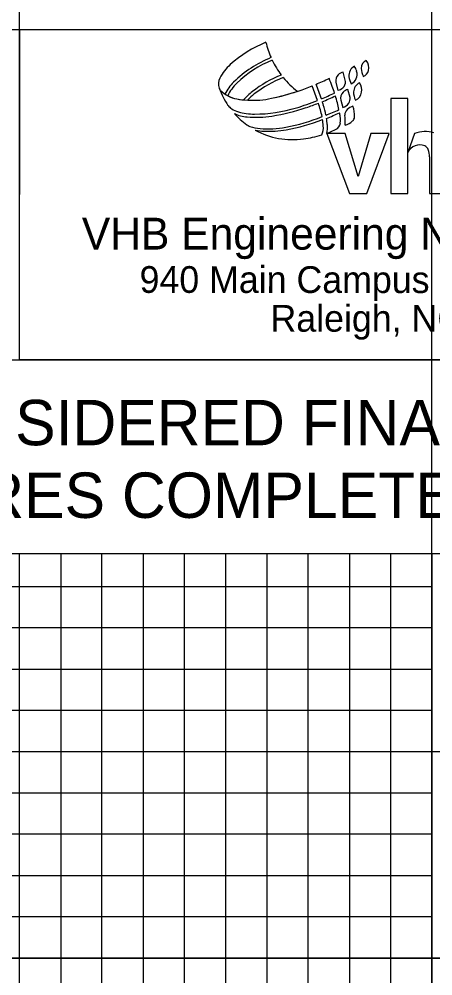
# Model space of a CAD drawing. Extents: x 1637092 to 1638792, y 884647 to 885778.
# Drawn here: x 1638666.6 to 1638716.8, y 885470 to 885585.9 of the extents above; entities that cross this region are included whole.
import ezdxf

# ---------------------------------------------------------------- set-up
doc = ezdxf.new("R2010")
doc.units = 0
for name, color, linetype in [('Default', 7, 'Continuous'), ('Scratch_Level_3', 7, 'Continuous'), ('Sheet DOT Grid CELL', 7, 'Continuous'), ('Sheet Layout Profile Border Port 1', 7, 'Continuous'), ('Sheet Plan And Profile CELL', 7, 'Continuous'), ('Sheet Profile CELL', 7, 'Continuous'), ('Sheet Profile Grid Major CELL', 7, 'Continuous'), ('Sheet Profile Grid Middle CELL', 7, 'Continuous'), ('Sheet Profile Grid Minor CELL', 7, 'Continuous')]:
    doc.layers.add(name, color=color, linetype=linetype)

msp = doc.modelspace()

# ---------------------------------------------------------------- linework, layer by layer
at = {"layer": 'Default'}
for p, q in [((1638706.2, 885578.33), (1638705.89, 885579.44)), ((1638705, 885578.23), (1638705.27, 885577.24)), ((1638702.77, 885576.02), (1638702.14, 885577.78)), ((1638706.75, 885576.37), (1638706.47, 885577.34)), ((1638705.6, 885576.04), (1638705.86, 885575.15)), ((1638713.75, 885576.25), (1638711.68, 885576.25)), ((1638711.68, 885576.25), (1638711.68, 885564.73)), ((1638703.92, 885572.02), (1638704.98, 885572.49)), ((1638706.14, 885572.02), (1638703.92, 885572.02)), ((1638703.92, 885572.02), (1638706.66, 885564.73)), ((1638707.71, 885566.81), (1638706.14, 885572.02)), ((1638709.27, 885572.02), (1638707.71, 885566.81)), ((1638708.75, 885564.73), (1638711.49, 885572.02)), ((1638711.49, 885572.02), (1638709.27, 885572.02)), ((1638714.56, 885572.02), (1638713.75, 885569.71)), ((1638716.36, 885569.18), (1638716.36, 885564.73)), ((1638706.66, 885564.73), (1638708.75, 885564.73)), ((1638711.68, 885564.73), (1638713.75, 885564.73)), ((1638716.36, 885564.73), (1638718.44, 885564.73)), ((1638566.62, 885544.59), (1638766.66, 885544.59)), ((1638566.62, 885544.59), (1638766.66, 885544.59)), ((1638766.66, 885521.09), (1638566.62, 885521.09)), ((1638766.66, 885521.09), (1638566.62, 885521.09))]:
    msp.add_line(p, q, dxfattribs=at)
msp.add_lwpolyline([(1638666.66, 885584.59), (1638766.66, 885584.59), (1638766.66, 885544.59), (1638666.66, 885544.59)], close=True, dxfattribs=at)
msp.add_lwpolyline([(1638713.75, 885564.73), (1638713.75, 885569.71), (1638713.75, 885576.25)], dxfattribs=at)
for centre, major_axis, start_param, end_param in [((1638701.85, 885569.72), (14.36, 0), 1.950459, 2.306295), ((1638706.82, 885585.5), (10.58, 0), 3.374816, 3.559712), ((1638696.12, 885576.05), (5.82, 0), 2.306295, 2.663056), ((1638702.4, 885568.25), (13.98, 0), 1.955908, 2.345415), ((1638702.4, 885568.25), (13.63, 0), 1.954608, 2.331375), ((1638706.82, 885585.5), (10.58, 0), 3.593328, 3.791245), ((1638709.07, 885579.95), (0.982, 0), 1.950799, 3.19085), ((1638707.66, 885579.99), (1.36, 0), 6.010502, 6.978239), ((1638704.08, 885565.1), (15.11, 0), 1.956929, 2.223843), ((1638706.01, 885578.38), (1.02, 0), 2.340862, 3.293303), ((1638706.19, 885578.19), (1.28, 0), 1.805558, 2.340862), ((1638707.87, 885579.04), (1.28, 0), 2.069357, 3.26373), ((1638706.31, 885579.17), (1.28, 0), 5.158115, 6.583255), ((1638705.16, 885578.82), (2.49, 0), 0.300085, 0.573578), ((1638710.58, 885580.02), (2.49, 0), 3.190836, 3.597778), ((1638707.95, 885579.91), (1.06, 0), 5.088672, 6.010509), ((1638692.29, 885578.03), (1.51, 0), 2.663056, 3.487291), ((1638696.32, 885574.46), (5.29, 0), 2.345415, 2.685879), ((1638696.39, 885574.56), (4.91, 0), 2.331375, 2.717794), ((1638704.08, 885565.1), (14.73, 0), 1.949325, 2.223843), ((1638706.82, 885585.5), (10.58, 0), 3.829221, 4.05458), ((1638690.89, 885605.83), (30.23, 0), 5.110242, 5.168312), ((1638667.51, 885563.96), (37.79, 0), 0.330018, 0.379866), ((1638667.51, 885563.96), (39.54, 0), 0.355324, 0.381952), ((1638705.18, 885578.3), (1.02, 0), 5.445151, 6.311085), ((1638709.07, 885579.19), (2.49, 0), 3.26373, 3.631752), ((1638708.37, 885577.03), (1.21, 0), 1.982585, 3.114577), ((1638706.57, 885577.26), (1.59, 0), 6.124862, 6.873863), ((1638699.76, 885580.72), (9.45, 0), 3.487291, 3.49224), ((1638691.6, 885577.74), (0.756, 0), 3.492238, 3.942132), ((1638691.6, 885577.74), (0.756, 0), 3.492238, 3.942132), ((1638699.76, 885580.72), (9.45, 0), 3.492238, 3.737263), ((1638693.65, 885579.85), (3.7, 0), 3.942115, 4.117328), ((1638693.65, 885579.85), (3.7, 0), 3.942115, 4.535322), ((1638699.03, 885571.7), (6.8, 0), 2.223843, 2.440018), ((1638699.03, 885571.7), (6.42, 0), 2.223843, 2.396036), ((1638690.89, 885605.83), (30.23, 0), 4.923489, 5.093727), ((1638690.89, 885605.83), (30.23, 0), 4.923489, 5.030725), ((1638690.89, 885605.83), (32.11, 0), 5.107726, 5.162272), ((1638686.31, 885570.93), (19.49, 0), 0.312292, 0.355324), ((1638705.01, 885578.5), (1.28, 0), 4.922279, 5.445148), ((1638706.55, 885576.29), (0.982, 0), 2.294387, 3.400315), ((1638706.85, 885575.95), (1.44, 0), 1.838184, 2.294391), ((1638709.28, 885577.01), (2.12, 0), 3.114567, 3.617561), ((1638706.87, 885577.21), (1.28, 0), 5.137017, 6.124854), ((1638693.65, 885579.85), (3.7, 0), 4.225969, 4.535322), ((1638694.93, 885586.99), (10.96, 0), 4.535322, 4.613027), ((1638694.93, 885586.99), (10.96, 0), 4.535322, 4.657076), ((1638694.93, 885586.99), (10.96, 0), 4.657076, 4.923489), ((1638694.93, 885586.99), (10.96, 0), 4.657076, 4.923489), ((1638690.89, 885605.83), (32.1, 0), 5.007435, 5.091777), ((1638690.89, 885605.83), (32.44, 0), 5.043468, 5.091439), ((1638692.94, 885572.1), (10.58, 0), 0.186675, 0.34709), ((1638690.89, 885605.83), (32.47, 0), 5.106941, 5.160619), ((1638667.51, 885563.96), (37.79, 0), 0.309699, 0.320394), ((1638686.31, 885570.93), (19.49, 0), 0.205325, 0.293478), ((1638705.4, 885576.51), (1.44, 0), 5.034707, 5.66976), ((1638705.77, 885576.25), (0.982, 0), 5.669754, 6.410867), ((1638693.19, 885576.27), (1.51, 0), 3.737263, 4.155114), ((1638694.07, 885577.68), (3.17, 0), 4.155114, 4.433304), ((1638695.11, 885581.31), (6.95, 0), 4.433304, 4.717272), ((1638695.06, 885592.12), (17.76, 0), 4.717272, 5.007435), ((1638693.57, 885598.02), (24.18, 0), 4.866042, 5.043468), ((1638692.94, 885572.1), (11.08, 0), 0.192744, 0.309699), ((1638690.89, 885605.83), (34.16, 0), 5.100586, 5.150688), ((1638690.89, 885605.83), (34.53, 0), 5.098273, 5.148033), ((1638686.31, 885570.93), (19.49, 0), 0.162521, 0.185756), ((1638706.94, 885574.28), (0.831, 0), 2.288613, 3.208516), ((1638707.78, 885573.31), (2.12, 0), 1.905419, 2.288613), ((1638703.59, 885574.1), (3.7, 0), 6.258511, 6.615609), ((1638694.66, 885578.69), (4.69, 0), 4.281835, 4.626581), ((1638699.76, 885580.72), (9.45, 0), 3.869789, 4.084312), ((1638695.34, 885586.6), (12.62, 0), 4.626581, 4.866042), ((1638694.81, 885595.06), (22.67, 0), 4.896065, 5.098239), ((1638695.49, 885593.33), (21.16, 0), 4.878361, 5.095384), ((1638692.94, 885572.1), (10.58, 0), 0.080866, 0.152313), ((1638692.94, 885572.1), (11.08, 0), 0.08898, 0.158557), ((1638704.58, 885573.39), (0.982, 0), 5.129856, 6.17953), ((1638702.55, 885573.6), (3.02, 0), 6.17953, 6.445706), ((1638699.89, 885573.42), (6.27, 0), 6.218327, 6.411973), ((1638705.56, 885575.04), (2.12, 0), 4.991009, 5.49053), ((1638706.47, 885574.13), (0.831, 0), 5.49053, 6.137671), ((1638695.09, 885574.3), (1.51, 0), 4.084312, 4.375641), ((1638696.22, 885577.51), (4.91, 0), 4.375641, 4.631331), ((1638696.62, 885579.24), (6.95, 0), 4.511808, 4.670453), ((1638699.76, 885580.72), (9.45, 0), 4.213149, 4.853258), ((1638696.78, 885584.44), (11.86, 0), 4.631331, 4.896065), ((1638696.87, 885585.13), (12.85, 0), 4.670453, 4.878361), ((1638701.23, 885572.77), (2.27, 0), 5.862276, 6.364042), ((1638700.22, 885572.75), (3.78, 0), 6.089473, 6.37216), ((1638715.86, 885568.75), (3.51, 0), 1.271815, 1.948427), ((1638698.8, 885587.45), (16.25, 0), 4.853258, 4.99278), ((1638715.19, 885569.04), (-1.59, 0), 4.330931, 5.84316), ((1638715.5, 885569.81), (-0.756, 0), 3.478495, 4.330931), ((1638713.72, 885569.18), (2.65, 0), 0, 0.336903)]:
    msp.add_ellipse(centre, major_axis=major_axis, ratio=0.999914, start_param=start_param, end_param=end_param, dxfattribs=at)
at = {"layer": 'Scratch_Level_3'}
msp.add_lwpolyline([(1637316.66, 885722.14), (1637316.66, 884697.14), (1638716.66, 884697.14), (1638716.66, 885777.71)], close=True, dxfattribs=at)
at = {"layer": 'Sheet DOT Grid CELL'}
for p, q in [((1638666.66, 885222.14), (1638666.66, 885521.09)), ((1638716.66, 885222.14), (1638716.66, 885521.09)), ((1638766.66, 885472.14), (1637266.66, 885472.14))]:
    msp.add_line(p, q, dxfattribs=at)
at = {"layer": 'Sheet Layout Profile Border Port 1'}
msp.add_lwpolyline([(1637316.66, 885561.09), (1637316.66, 885222.14), (1638716.66, 885222.14), (1638716.66, 885521.09)], dxfattribs=at)
at = {"layer": 'Sheet Plan And Profile CELL'}
for p, q in [((1638666.63, 885697.09), (1638666.63, 885584.59)), ((1638666.66, 885584.59), (1638666.64, 885544.59)), ((1638566.62, 885544.59), (1638766.66, 885544.59))]:
    msp.add_line(p, q, dxfattribs=at)
at = {"layer": 'Sheet Profile CELL'}
msp.add_lwpolyline([(1638566.61, 885697.09), (1638566.61, 885584.59), (1638766.66, 885584.59)], dxfattribs=at)
at = {"layer": 'Sheet Profile Grid Major CELL'}
for points in [[(1638716.66, 885521.09), (1638716.66, 885222.14), (1638766.66, 885222.14), (1638766.66, 885572.14)], [(1638566.62, 885522.14), (1637266.66, 885522.14), (1637266.66, 885472.14), (1638766.66, 885472.14)], [(1638616.66, 885521.09), (1638616.66, 885222.14), (1638666.66, 885222.14), (1638666.66, 885222.14), (1638666.66, 885521.09)]]:
    msp.add_lwpolyline(points, dxfattribs=at)
at = {"layer": 'Sheet Profile Grid Middle CELL'}
for points in [[(1638641.66, 885484.94), (1638641.66, 885222.14), (1638691.66, 885222.14), (1638691.66, 885521.09)], [(1638591.66, 885497.14), (1638766.66, 885497.14)]]:
    msp.add_lwpolyline(points, dxfattribs=at)
at = {"layer": 'Sheet Profile Grid Minor CELL'}
for p, q in [((1638716.66, 885512.14), (1637316.66, 885512.14)), ((1637316.66, 885507.14), (1638716.66, 885507.14)), ((1638716.66, 885487.14), (1637316.66, 885487.14)), ((1637316.66, 885482.14), (1638716.66, 885482.14)), ((1638716.66, 885477.14), (1637316.66, 885477.14))]:
    msp.add_line(p, q, dxfattribs=at)
for points in [[(1638566.62, 885527.14), (1637316.66, 885527.14), (1637316.66, 885517.14), (1638716.66, 885517.14)], [(1638671.66, 885521.09), (1638671.66, 885222.14), (1638676.66, 885222.14), (1638676.66, 885521.09)], [(1638681.66, 885521.09), (1638681.66, 885222.14), (1638686.66, 885222.14), (1638686.66, 885521.09)], [(1638696.66, 885521.09), (1638696.66, 885222.14), (1638701.66, 885222.14), (1638701.66, 885521.09)], [(1638706.66, 885521.09), (1638706.66, 885222.14), (1638711.66, 885222.14), (1638711.66, 885521.09)], [(1638716.66, 885502.14), (1637316.66, 885502.14), (1637316.66, 885492.14), (1638716.66, 885492.14)]]:
    msp.add_lwpolyline(points, dxfattribs=at)

# ---------------------------------------------------------------- texts
at = {"layer": 'Default'}
for s, height, rotation, p in [('VHB Engineering NC, P.C. (C-3705)', 3.8596, 360, (1638674.22, 885557.95)), ('940 Main Campus Drive, Suite 500', 3.2388, 359.9612, (1638681.22, 885552.71)), ('Raleigh, NC 27606', 3.2388, 359.9612, (1638697.09, 885548.01)), ('DOCUMENT NOT CONSIDERED FINAL', 5.5, 360, (1638587.69, 885534.25)), ('DOCUMENT NOT CONSIDERED FINAL', 5.5, 360, (1638587.69, 885534.25)), ('UNLESS ALL SIGNATURES COMPLETED', 5.5, 360, (1638582.62, 885525.45)), ('UNLESS ALL SIGNATURES COMPLETED', 5.5, 360, (1638582.62, 885525.45))]:
    msp.add_text(s, height=height, rotation=rotation, dxfattribs=at).set_placement(p)

doc.saveas('drawing.dxf')
